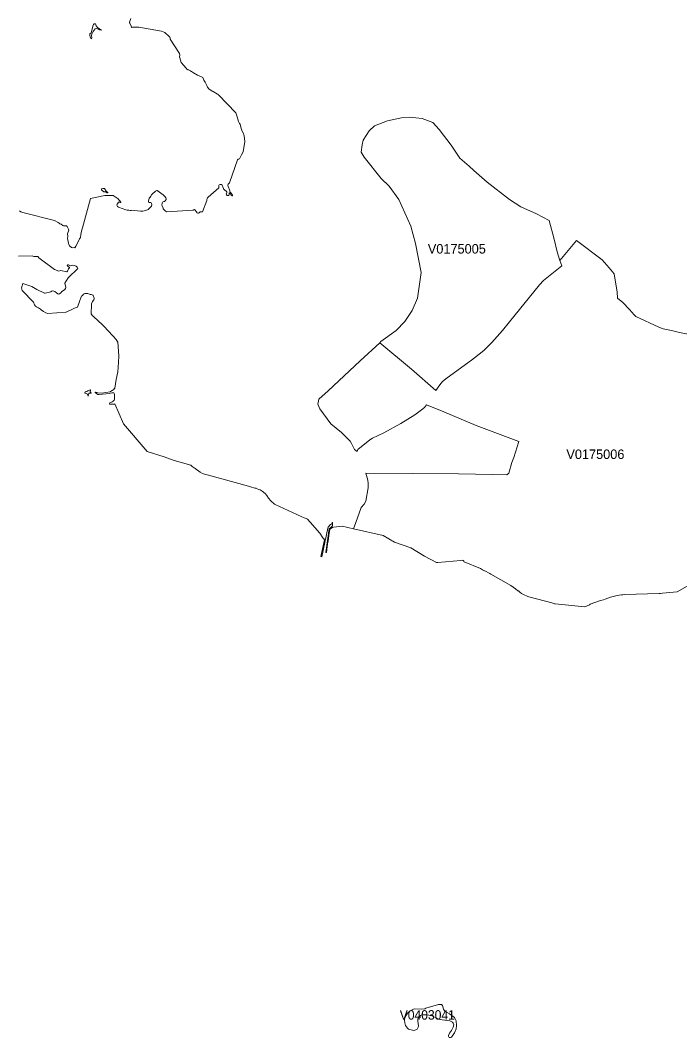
# Model space of a CAD drawing. Extents: x 369010 to 735936, y 6377141 to 6616555.
# Drawn here: x 411133 to 418064, y 6501624 to 6512310 of the extents above; entities that cross this region are included whole.
import ezdxf
from ezdxf.enums import TextEntityAlignment as Align

# ---------------------------------------------------------------- set-up
doc = ezdxf.new("R2010")
doc.units = 0
doc.header["$LTSCALE"] = 40
doc.layers.add('3', color=7, linetype='Continuous', lineweight=13)
doc.layers.add('4', color=7, linetype='Continuous')

msp = doc.modelspace()

# ---------------------------------------------------------------- linework, layer by layer
at = {"layer": '3'}
for points in [[(411896.6, 6512247.36), (411882.53, 6512188.28), (411877.56, 6512180), (411863.49, 6512167.92), (411863.49, 6512150.38), (411867.14, 6512138.46), (411873.42, 6512119.92), (411880.54, 6512114.63), (411883.52, 6512127.37), (411881.87, 6512153.85), (411885.51, 6512164.28), (411900.24, 6512191.75), (411921.09, 6512220.88), (411936.81, 6512223.2), (411964.29, 6512208.8), (411983.15, 6512205.49), (411985.8, 6512208.47), (411946.58, 6512232.63), (411931.85, 6512252.66), (411922.08, 6512273.84), (411909.34, 6512272.85), (411903.71, 6512266.89)], [(414913.9, 6508921.23), (415245.4, 6508644.84), (415500.44, 6508421.24), (415541.82, 6508481.15), (415571.28, 6508514.92), (415620.1, 6508554.97), (415874.81, 6508741.33), (415988.52, 6508826.39), (416010.03, 6508844.6), (416091.46, 6508926.03), (416203.67, 6509052.8), (416275.17, 6509143), (416590.62, 6509531.44), (416634.31, 6509577.45), (416825.64, 6509730.54), (416803.62, 6509786.32), (416776.32, 6509877.35), (416743.71, 6510011.24), (416693.07, 6510208.85), (416559.84, 6510276.21), (416395.16, 6510352.51), (416276.66, 6510428.8), (416040.48, 6510610.86), (415901.96, 6510731.35), (415851.64, 6510779.51), (415753.34, 6510863.91), (415660.98, 6511000.46), (415536.52, 6511165.13), (415468.17, 6511237.46), (415357.78, 6511277.51), (415290.25, 6511285.12), (415220.74, 6511294.56), (415139.65, 6511286.28), (414994.17, 6511253.18), (414856.97, 6511201.87), (414799.04, 6511150.57), (414736.15, 6511049.78), (414726.22, 6511003.77), (414717.94, 6510924.32), (414746.08, 6510871.36), (414928.13, 6510649.75), (415010.72, 6510568.66), (415111.68, 6510428.14), (415238.95, 6510148.61), (415288.6, 6509966.55), (415348.35, 6509660.2), (415308.63, 6509390.43), (415254.01, 6509261.5), (415174.57, 6509145.65), (415083.71, 6509051.48), (414923.33, 6508935.63)], [(412002.02, 6510544.16), (411988.28, 6510541.02), (411986.96, 6510530.42), (411989.61, 6510526.29), (412012.12, 6510507.92), (412027.34, 6510509.41), (412046.54, 6510497.49), (412053.33, 6510497.16), (412052, 6510502.45), (412034.96, 6510516.69), (412018.74, 6510542.67)], [(411844.63, 6508418.59), (411833.21, 6508409.66), (411815.17, 6508406.18), (411810.53, 6508398.9), (411815, 6508393.11), (411835.86, 6508386.49), (411845.79, 6508361.66), (411852.41, 6508389.3), (411857.04, 6508393.77), (411876.07, 6508395.42), (411878.56, 6508398.4), (411866.31, 6508406.51), (411871.77, 6508424.05), (411869.12, 6508427.86)], [(415347.02, 6501921.4), (415272.88, 6501924.71), (415258.64, 6501920.58), (415231.5, 6501905.51), (415203.37, 6501879.36), (415176.22, 6501837), (415171.42, 6501808.69), (415175.4, 6501780.39), (415183.84, 6501752.09), (415191.28, 6501736.2), (415202.21, 6501723.29), (415214.45, 6501714.19), (415242.76, 6501704.92), (415271.06, 6501699.96), (415292.24, 6501704.43), (415303.99, 6501712.87), (415317.07, 6501733.22), (415319.71, 6501747.46), (415312.93, 6501796.94), (415312.93, 6501818.13), (415321.04, 6501840.8), (415338.25, 6501857.52), (415354.64, 6501861.66), (415411.24, 6501862.32), (415460.72, 6501854.54), (415531.06, 6501818.46), (415566.15, 6501810.68), (415647.74, 6501801.25), (415676.71, 6501785.69), (415683.99, 6501775.92), (415689.29, 6501758.05), (415683.99, 6501733.56), (415666.28, 6501699.63), (415644.27, 6501670.83), (415635.99, 6501647.82), (415635.33, 6501638.06), (415642.45, 6501626.64), (415654.86, 6501623.66), (415665.95, 6501629.29), (415697.23, 6501675.79), (415714.11, 6501716.84), (415719.41, 6501752.09), (415714.61, 6501799.26), (415695.74, 6501834.02), (415682, 6501847.59), (415645.1, 6501875.23), (415595.28, 6501903.2), (415583.03, 6501922.73), (415569.79, 6501960.13), (415561.52, 6501970.72), (415546.12, 6501973.04), (415527.92, 6501970.39), (415397.34, 6501933.32), (415386.25, 6501927.86)]]:
    msp.add_lwpolyline(points, close=True, dxfattribs=at)
for points in [[(412293.31, 6512327.96), (412282.22, 6512291.55), (412281.06, 6512285.43), (412282.88, 6512280.79), (412298.44, 6512248.02), (412300.92, 6512239.58), (412306.05, 6512235.45), (412312.84, 6512237.43), (412368.78, 6512237.93), (412378.38, 6512237.93), (412618.69, 6512195.39), (412652.62, 6512182.48), (412698.46, 6512140.45), (412703.43, 6512132.01), (412707.73, 6512122.08), (412709.22, 6512110.99), (412806.04, 6511962.2), (412810.51, 6511944.99), (412807.86, 6511926.45), (412810.34, 6511914.7), (412825.73, 6511868.85), (412878.03, 6511808.28), (412888.13, 6511793.88), (412893.09, 6511792.72), (412898.89, 6511791.23), (412906.5, 6511786.6), (412920.73, 6511778.16), (412924.71, 6511775.01), (412933.48, 6511772.7), (412953.01, 6511760.45), (412994.22, 6511732.98), (413001.83, 6511729.5), (413032.45, 6511721.23), (413045.03, 6511714.44), (413050.49, 6511708.32)], [(413050.49, 6511708.32), (413057.44, 6511692.59), (413063.07, 6511680.35), (413068.69, 6511670.42), (413074.98, 6511660.65), (413092.36, 6511624.41), (413099.97, 6511609.18), (413113.38, 6511589.98), (413148.8, 6511567.31), (413161.71, 6511561.18), (413206.89, 6511533.71), (413217.48, 6511527.25), (413399.21, 6511338.91), (413412.94, 6511296.21), (413426.35, 6511249.21), (413435.12, 6511233.65), (413436.61, 6511228.19), (413443.06, 6511217.93), (413456.14, 6511173.9), (413458.95, 6511161.49), (413460.11, 6511156.53), (413462.26, 6511151.4), (413466.9, 6511146.6), (413478.98, 6511121.27), (413481.46, 6511107.21), (413486.43, 6511098.6), (413492.72, 6511038.36), (413474.18, 6510928.79), (413459.62, 6510898.67), (413440.42, 6510861.27), (413436.44, 6510855.97), (413423.87, 6510850.84), (413416.25, 6510844.05), (413333.5, 6510602.25), (413324.07, 6510595.8), (413319.76, 6510590.34), (413315.46, 6510579.91), (413317.94, 6510566.5), (413325.23, 6510548.8), (413328.87, 6510540.02), (413333.5, 6510528.44), (413334.16, 6510518.67), (413336.31, 6510512.88), (413340.45, 6510506.43), (413351.21, 6510493.68), (413358.16, 6510483.59), (413364.28, 6510475.15), (413364.95, 6510467.2), (413361.8, 6510465.05), (413355.68, 6510465.05), (413350.22, 6510471.17), (413338.63, 6510492.69), (413330.69, 6510497.32), (413329.2, 6510495.5), (413328.37, 6510477.3), (413325.56, 6510470.84), (413318.94, 6510469.35), (413308.18, 6510471.67), (413299.41, 6510475.97), (413296.59, 6510484.58), (413305.2, 6510500.14), (413305.53, 6510507.75), (413276.9, 6510531.75), (413268.95, 6510537.87), (413267.3, 6510544), (413249.92, 6510585.37), (413240.49, 6510587.36), (413232.71, 6510585.37), (413224.93, 6510580.57), (413220.79, 6510573.79), (413219.14, 6510566.5), (413220.79, 6510551.61), (413109.57, 6510454.29), (413104.11, 6510447.84), (413101.3, 6510444.03), (413097.66, 6510435.09), (413092.69, 6510428.14), (413093.69, 6510416.89), (413046.68, 6510297.89), (413033.94, 6510299.55), (413023.84, 6510298.22), (413013.42, 6510286.97), (413007.95, 6510285.48), (412997.86, 6510285.81), (412989.42, 6510289.12), (412987.6, 6510293.59), (412981.14, 6510301.04), (412970.22, 6510317.42), (412962.44, 6510321.72), (412954.99, 6510321.06), (412950.19, 6510316.76), (412670, 6510299.71), (412666.02, 6510301.53), (412656.09, 6510308.65), (412644.67, 6510319.41), (412636.07, 6510331.65), (412633.92, 6510337.94), (412623.16, 6510359.95), (412622.16, 6510369.89), (412623.32, 6510388.26)], [(414994.17, 6511253.18), (415139.65, 6511286.28), (415220.74, 6511294.56), (415290.25, 6511285.12), (415357.78, 6511277.51), (415468.17, 6511237.46), (415536.52, 6511165.13), (415660.98, 6511000.46), (415753.34, 6510863.91), (415851.64, 6510779.51), (415901.96, 6510731.35), (416040.48, 6510610.86), (416276.66, 6510428.8), (416395.16, 6510352.51), (416559.84, 6510276.21), (416693.07, 6510208.85), (416743.71, 6510011.24), (416776.32, 6509877.35), (416803.62, 6509786.32), (416979.06, 6509996.51), (417251.15, 6509794.76), (417323.31, 6509711.51), (417376.1, 6509647.46), (417382.39, 6509602.61), (417408.04, 6509458.62), (417409.7, 6509392.92), (417465.64, 6509346.57), (417536.14, 6509272.92), (417585.8, 6509216.82), (417604.17, 6509199.61), (417846.63, 6509087.56), (417889.83, 6509068.36), (417979.53, 6509053.14), (418062.78, 6509032.28), (418190.38, 6509007.79)], [(413637.53, 6507381.71), (413654.08, 6507377.74), (413675.76, 6507362.84), (413706.71, 6507339.67), (413724.42, 6507319.65), (413743.29, 6507289.86), (413765.96, 6507261.06), (413804.69, 6507227.79), (413812.97, 6507223.32), (414087.04, 6507096.55), (414115.84, 6507084.47), (414138.51, 6507075.53), (414150.59, 6507068.91), (414178.9, 6507040.11), (414280.18, 6506923.93), (414314.44, 6506875.76), (414325.04, 6506863.02), (414329.5, 6506852.43), (414292.43, 6506676.33), (414302.36, 6506673.02), (414365.42, 6506976.39), (414369.23, 6506985.33), (414392.06, 6507010.82), (414395.37, 6507012.97), (414404.15, 6507017.93), (414406.96, 6507026.21), (414409.77, 6507033.99), (414414.74, 6507033.99), (414416.39, 6507027.86), (414415.24, 6506999.73), (414409.11, 6506994.1), (414394.22, 6506980.86), (414379.82, 6506972.09), (414343.24, 6506721.18), (414351.02, 6506720.19), (414362.6, 6506810.89), (414368.23, 6506838.69), (414376.51, 6506900.09), (414388.09, 6506963.65), (414415.73, 6506983.67), (414424.17, 6506985.33), (414516.03, 6506995.76), (414635.52, 6506969.11), (414660.02, 6507034.98), (414717.94, 6507191.22), (414748.89, 6507228.12), (414763.62, 6507259.07), (414790.27, 6507398.43), (414789.44, 6507444.77), (414786.46, 6507479.36), (414777.69, 6507506), (414765.94, 6507554.99), (415740.92, 6507546.06), (416097.58, 6507540.26), (416246.37, 6507534.31), (416269.21, 6507554.99), (416298.67, 6507666.21), (416319.36, 6507717.02), (416375.3, 6507887.33), (415924.14, 6508053.66), (415584.85, 6508196.49), (415403.63, 6508270.8), (415381.45, 6508244.32), (415349.84, 6508218.5), (415279.83, 6508166.2), (415132.2, 6508074.18), (414953.95, 6507976.86), (414833.79, 6507920.1), (414807.31, 6507904.7), (414682.69, 6507801.59), (414675.41, 6507780.08), (414646.61, 6507802.26), (414615.66, 6507865.64), (414599.28, 6507890.64), (414511.06, 6507981.17), (414396.37, 6508073.02), (414281.67, 6508229.92), (414259.99, 6508277.09), (414270.92, 6508331.37), (414368.4, 6508418.1), (414706.52, 6508733.22), (414913.9, 6508921.23), (414923.33, 6508935.63), (415083.71, 6509051.48), (415174.57, 6509145.65), (415254.01, 6509261.5), (415308.63, 6509390.43), (415348.35, 6509660.2), (415288.6, 6509966.55), (415238.95, 6510148.61), (415111.68, 6510428.14), (415010.72, 6510568.66), (414928.13, 6510649.75), (414746.08, 6510871.36), (414717.94, 6510924.32), (414726.22, 6511003.77), (414736.15, 6511049.78), (414799.04, 6511150.57), (414856.97, 6511201.87), (414994.17, 6511253.18)], [(412623.32, 6510388.26), (412624.81, 6510394.21), (412628.45, 6510399.51), (412635.9, 6510402.99), (412643.35, 6510405.47), (412649.47, 6510408.61), (412656.42, 6510415.23), (412666.69, 6510426.65), (412666.19, 6510438.07), (412662.71, 6510447.01), (412654.44, 6510456.28), (412633.09, 6510478.12), (412573.34, 6510523.14), (412568.38, 6510522.65), (412555.8, 6510515.36), (412520.55, 6510485.74), (412513.26, 6510477.79), (412504.49, 6510462.24), (412496.71, 6510454.29), (412489.1, 6510443.53), (412483.31, 6510426.16), (412479.67, 6510412.59), (412480.49, 6510403.65), (412483.64, 6510398.19), (412486.45, 6510397.36), (412496.71, 6510397.19), (412503, 6510395.87), (412508.63, 6510391.73), (412512.93, 6510384.45), (412515.41, 6510374.19), (412513.26, 6510359.46), (412508.46, 6510354.16), (412475.69, 6510323.71), (412469.24, 6510318.41), (412460.3, 6510314.61), (412419.42, 6510306.17), (412409.82, 6510305.17), (412396.91, 6510304.84), (412305.22, 6510315.93), (412296.78, 6510313.94), (412287.02, 6510313.94), (412272.45, 6510316.43), (412257.39, 6510317.59), (412241.01, 6510318.08), (412165.04, 6510347.54), (412155.44, 6510355.65), (412148.82, 6510367.9), (412149.65, 6510378.16), (412154.45, 6510383.79), (412161.07, 6510392.39), (412163.22, 6510396.37), (412166.7, 6510399.34), (412174.48, 6510400.01), (412181.1, 6510397.69), (412186.89, 6510395.04), (412189.54, 6510397.69), (412190.03, 6510400.5), (412174.81, 6510416.72), (412170.5, 6510424.5), (412160.24, 6510436.91), (412110.43, 6510470.68), (412103.97, 6510471.84), (412021.22, 6510469.85), (411872.43, 6510439.73), (411787.36, 6510129.9), (411782.4, 6510118.82), (411774.12, 6510082.57), (411770.48, 6510055.76), (411764.52, 6510030.11), (411756.74, 6510014.05), (411737.38, 6509975.16), (411716.86, 6509936.76), (411707.42, 6509920.38), (411704.11, 6509923.19), (411676.48, 6509920.38), (411670.68, 6509922.36), (411651.82, 6509942.22), (411644.53, 6509958.11), (411639.9, 6509965.89), (411635.43, 6509991.87), (411630.46, 6510014.88), (411631.95, 6510042.19), (411630.3, 6510066.52), (411631.95, 6510078.27), (411640.23, 6510095.98), (411643.21, 6510105.91), (411640.4, 6510117), (411632.45, 6510130.57), (411626.82, 6510143.31), (411616.89, 6510152.91), (411604.48, 6510152.91), (411585.61, 6510152.91), (411580.48, 6510154.07), (411563.6, 6510170.12), (411550.2, 6510172.27), (411542.42, 6510178.89), (411532.49, 6510186.67), (411492.93, 6510207.69), (411158.12, 6510293.26), (411138.92, 6510299.05)], [(411138.92, 6510299.05), (411123.53, 6510307.66)], [(418190.38, 6509007.79), (418062.78, 6509032.28), (417979.53, 6509053.14), (417889.83, 6509068.36), (417846.63, 6509087.56), (417604.17, 6509199.61), (417585.8, 6509216.82), (417536.14, 6509272.92), (417465.64, 6509346.57), (417409.7, 6509392.92), (417408.04, 6509458.62), (417382.39, 6509602.61), (417376.1, 6509647.46), (417323.31, 6509711.51), (417251.15, 6509794.76), (416979.06, 6509996.51), (416803.62, 6509786.32)], [(411112.44, 6509833.82), (411256.92, 6509837.96), (411265.2, 6509831.83), (411273.97, 6509830.18), (411298.63, 6509829.68), (411315.84, 6509830.18), (411319.98, 6509826.87), (411327.76, 6509815.78), (411490.95, 6509692.15), (411538.28, 6509676.59), (411555.82, 6509682.88), (411622.52, 6509666.82), (411629.97, 6509674.6), (411634.11, 6509682.38), (411637.09, 6509693.47), (411640.4, 6509698.44), (411644.53, 6509704.06), (411649.83, 6509711.18), (411649, 6509716.14), (411640.4, 6509721.11), (411628.31, 6509730.05), (411626.82, 6509736.17), (411628.81, 6509741.14), (411633.28, 6509742.46), (411638.74, 6509742.46), (411648.17, 6509738.65), (411662.08, 6509732.69), (411671.18, 6509733.36), (411685.08, 6509737), (411700.47, 6509734.35), (411720.66, 6509727.56), (411730.1, 6509719.12), (411736.55, 6509702.9), (411637.42, 6509603.77), (411602.83, 6509550.97), (411611.43, 6509504.46), (411607.46, 6509491.72), (411600.34, 6509482.78), (411585.61, 6509471.53), (411569.06, 6509460.61), (411558.47, 6509448.69), (411546.39, 6509437.44), (411535.63, 6509435.45), (411528.02, 6509437.44), (411514.61, 6509447.37), (411497.07, 6509460.61), (411485.48, 6509465.74), (411473.07, 6509468.38), (411461.65, 6509464.58), (411452.55, 6509459.28), (411394.13, 6509442.9), (411386.18, 6509443.56), (411308.39, 6509481.46), (411271.32, 6509504.63), (411255.27, 6509513.57), (411159.77, 6509547.5), (411148.68, 6509509.43), (411146.53, 6509501.65), (411153.65, 6509471.2), (411270.16, 6509348.23), (411281.75, 6509320.92), (411291.51, 6509308.67), (411301.94, 6509300.89)], [(416803.62, 6509786.32), (416825.64, 6509730.54), (416634.31, 6509577.45), (416590.62, 6509531.44), (416275.17, 6509143), (416203.67, 6509052.8), (416091.46, 6508926.03), (416010.03, 6508844.6), (415988.52, 6508826.39), (415874.81, 6508741.33), (415620.1, 6508554.97), (415571.28, 6508514.92), (415541.82, 6508481.15), (415500.44, 6508421.24), (415245.4, 6508644.84), (414913.9, 6508921.23), (414706.52, 6508733.22), (414368.4, 6508418.1), (414270.92, 6508331.37), (414259.99, 6508277.09), (414281.67, 6508229.92), (414396.37, 6508073.02), (414511.06, 6507981.17), (414599.28, 6507890.64), (414615.66, 6507865.64), (414646.61, 6507802.26), (414675.41, 6507780.08), (414682.69, 6507801.59), (414807.31, 6507904.7), (414833.79, 6507920.1), (414953.95, 6507976.86), (415132.2, 6508074.18), (415279.83, 6508166.2), (415349.84, 6508218.5), (415381.45, 6508244.32), (415403.63, 6508270.8), (415584.85, 6508196.49), (415924.14, 6508053.66), (416375.3, 6507887.33), (416319.36, 6507717.02), (416298.67, 6507666.21), (416269.21, 6507554.99), (416246.37, 6507534.31), (416097.58, 6507540.26), (415740.92, 6507546.06), (414765.94, 6507554.99), (414777.69, 6507506), (414786.46, 6507479.36), (414789.44, 6507444.77), (414790.27, 6507398.43), (414763.62, 6507259.07), (414748.89, 6507228.12), (414717.94, 6507191.22), (414660.02, 6507034.98), (414635.52, 6506969.11), (414948.32, 6506898.94), (415066.66, 6506826.94), (415237.79, 6506768.85), (415382.77, 6506681.46), (415509.55, 6506615.59), (415522.79, 6506613.28), (415764.75, 6506635.95), (415779.65, 6506638.76), (415787.93, 6506637.11), (415795.7, 6506628.17), (415799.01, 6506621.05), (415971.8, 6506553.03), (415991.16, 6506538.63), (416012.18, 6506526.39), (416017.64, 6506526.39), (416070.28, 6506498.08), (416080.7, 6506492.13), (416289.4, 6506372.47), (416339.22, 6506339.86), (416364.71, 6506317.69), (416370.17, 6506316.03), (416385.73, 6506304.45), (416402.28, 6506290.54), (416422.3, 6506280.12), (416469.31, 6506257.94), (416478.74, 6506254.63), (416491.48, 6506252.31), (416719.55, 6506192.07), (416748.84, 6506181.48), (416757.12, 6506179.32), (417067.6, 6506149.37), (417078.19, 6506152.68), (417092.1, 6506159.96), (417115.76, 6506172.04), (417124.2, 6506177.67), (417231.45, 6506216.89), (417262.57, 6506224.18), (417282.43, 6506230.8), (417308.41, 6506239.57), (417337.87, 6506250.16), (417364.35, 6506256.78), (417408.71, 6506267.37), (417427.41, 6506270.68), (417452.9, 6506274.99), (417466.14, 6506275.65)], [(411301.94, 6509300.89), (411322.79, 6509291.79), (411335.7, 6509284.34), (411346.79, 6509275.74), (411353.74, 6509267.79), (411376.91, 6509250.91), (411402.4, 6509237.84), (411422.43, 6509231.71), (411610.27, 6509243.13), (411615.9, 6509245.62), (411695.01, 6509284.68), (411701.63, 6509286.83), (411735.73, 6509296.76), (411756.08, 6509357.99), (411773.63, 6509404.17), (411777.76, 6509412.28), (411786.04, 6509420.06), (411797.46, 6509432.8), (411809.87, 6509440.75), (411825.26, 6509442.4), (411843.3, 6509440.41), (411867.63, 6509431.81), (411878.56, 6509429.66), (411887.33, 6509428.33), (411897.26, 6509422.71), (411900.57, 6509418.57), (411910, 6509392.92), (411910.33, 6509380.17), (411906.19, 6509372.89), (411891.13, 6509356.84), (411882.86, 6509331.68), (411879.88, 6509325.39), (411878.56, 6509227.41), (411886.5, 6509216.49), (411891.46, 6509207.05), (411898.75, 6509201.92), (411906.69, 6509196.13), (411991.93, 6509115.86), (411999.7, 6509108.91), (412011.95, 6509098.98), (412104.3, 6508995.04), (412143.03, 6508954.66), (412144.19, 6508949.7), (412156.6, 6508930.33), (412168.52, 6508785.52), (412165.7, 6508714.51), (412157.76, 6508619.51), (412141.04, 6508537.92), (412126.15, 6508447.06), (412119.86, 6508437.96), (412112.58, 6508429.68), (412102.32, 6508425.54), (412079.15, 6508408.5), (411986.13, 6508393.44), (411947.74, 6508395.59), (411936.32, 6508401.05), (411923.9, 6508405.02), (411920.59, 6508402.7), (411920.26, 6508398.57), (411921.92, 6508397.24), (411926.55, 6508396.75), (411931.68, 6508393.93), (411936.65, 6508387.48), (411949.06, 6508381.19), (411962.13, 6508379.04), (412070.54, 6508390.29), (412093.55, 6508396.91), (412109.76, 6508398.57), (412115.72, 6508395.92), (412122.84, 6508382.51), (412124.83, 6508364.31), (412124.83, 6508342.13), (412122.84, 6508327.23), (412119.03, 6508320.78), (412110.43, 6508309.53), (412100.17, 6508303.4), (412075.01, 6508292.64), (412069.22, 6508286.85), (412069.71, 6508279.9), (412079.15, 6508277.42), (412090.4, 6508278.25), (412104.3, 6508277.91), (412123.34, 6508277.91), (412126.81, 6508280.23), (412216.18, 6508072.86), (412467.75, 6507782.4), (412645.17, 6507725.96), (412751.92, 6507686.73), (412926.53, 6507635.76), (412940.1, 6507623.02), (412972.21, 6507602.49), (413023.18, 6507564.92), (413047.51, 6507550.03), (413070.18, 6507543.24), (413110.57, 6507531.66), (413530.78, 6507415.97), (413553.95, 6507411.5), (413598.8, 6507396.11), (413611.05, 6507394.95), (413637.53, 6507381.71)], [(417466.14, 6506275.65), (417485.5, 6506279.45), (417849.28, 6506290.54), (417864.17, 6506290.54), (417882.38, 6506292.69), (418038.61, 6506308.25), (418639.06, 6506651.01)]]:
    msp.add_lwpolyline(points, dxfattribs=at)

# ---------------------------------------------------------------- texts
at = {"layer": '4'}
for s, p in [('V0175005', (415721.82, 6509860.25)), ('V0175006', (417178.43, 6507702.24))]:
    msp.add_text(s, height=100, dxfattribs=at).set_placement(p, align=Align.CENTER)
at = {"layer": '4', "width": 0.95}
msp.add_text('V0403041', height=100, dxfattribs=at).set_placement((415411.23, 6501812.32), align=Align.CENTER)

doc.saveas('drawing.dxf')
